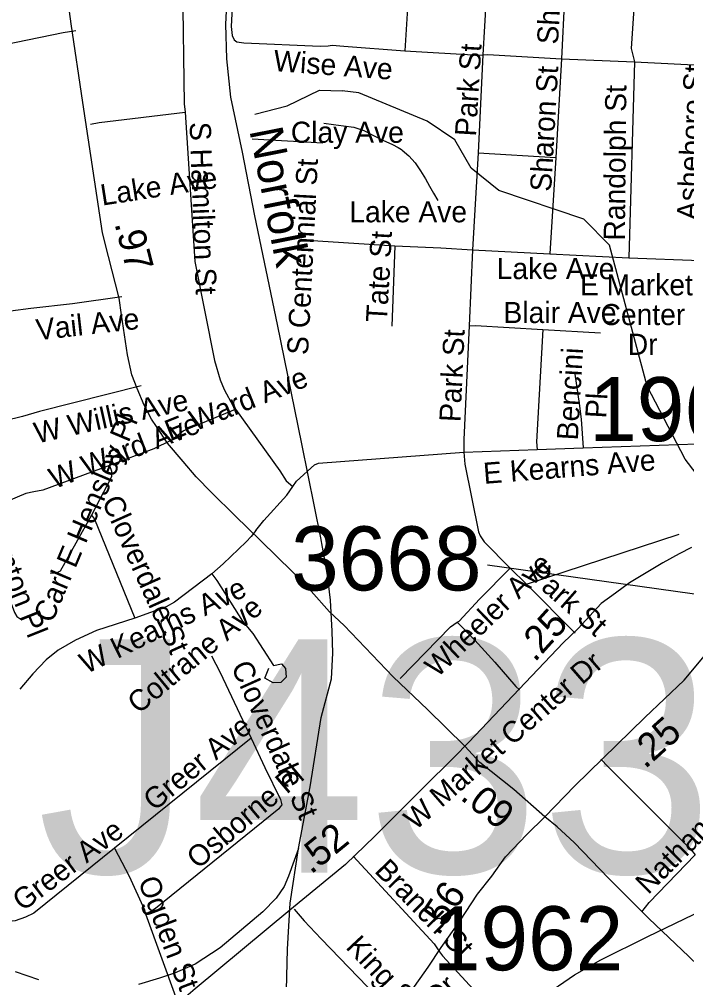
# Model space of a CAD drawing. Extents: x 1662474 to 1856135, y 779280 to 917889.
# Drawn here: x 1702628 to 1705631, y 797474 to 801794 of the extents above; entities that cross this region are included whole.
import ezdxf

# ---------------------------------------------------------------- set-up
doc = ezdxf.new("R2010")
doc.units = 0
for name, color, linetype in [('Cogo Default Point CELL', 7, 'Continuous'), ('Exist Hydrographic Misc Water Feature', 7, 'Continuous'), ('Exist Railroad Mainline', 7, 'Continuous'), ('Exist Railroad Mainline Label', 7, 'Continuous'), ('Exist Railroad Siding', 7, 'Continuous'), ('Exist Road Non-System Structure Non-Sys Other Number Label', 7, 'Continuous'), ('Exist Road Non-System Type 51', 7, 'Continuous'), ('Exist Road Non-System Type 51 Label', 7, 'Continuous'), ('Exist Road Primary US Mileage Hundredths English Label', 7, 'Continuous'), ('Exist Road Primary US UnDivided 4 Lane Attributed', 7, 'Continuous'), ('Exist Road Secondary Mileage Tenths English Label', 7, 'Continuous'), ('Exist Road Secondary Type 51 Attributed', 7, 'Continuous'), ('Exist Road Secondary Type 51 Label', 7, 'Continuous'), ('Exist Utilities Electrical Transmission Line', 7, 'Continuous'), ('Prop DGN Element Guardrail', 7, 'Continuous')]:
    doc.layers.add(name, color=color, linetype=linetype)

msp = doc.modelspace()

# ---------------------------------------------------------------- linework, layer by layer
at = {"layer": 'Cogo Default Point CELL'}
msp.add_line((1705743.6, 799197.4), (1704734.2, 799337.9), dxfattribs=at)
at = {"layer": 'Exist Hydrographic Misc Water Feature'}
for points in [[(1703687, 801367.3), (1703833.3, 801403.9), (1703978.1, 801474.6), (1704081, 801471.1)], [(1706601, 798213), (1706577, 798348), (1706572, 798673.1), (1706483, 799006.4), (1706318, 799183.7), (1706094, 799326.1), (1705772, 799621.6), (1705624, 799814.9), (1705452, 800143.4), (1705283, 800777), (1705167, 800894.3), (1704785, 801023.5), (1704661, 801124.5), (1704587, 801250.7), (1704463, 801335.3), (1704156, 801463), (1704081, 801471.1)]]:
    msp.add_lwpolyline(points, dxfattribs=at)
at = {"layer": 'Exist Railroad Mainline'}
for points in [[(1703884.2, 798063.9), (1703936.3, 798341.8), (1703986.3, 798653.6), (1704032.5, 798827.7), (1704039.1, 798943.5), (1704035.5, 799041.7), (1704028.2, 799181.7), (1704015.1, 799293.9), (1703984, 799461.9), (1703898.4, 799884.8), (1703789.5, 800421.4), (1703688.2, 800909.9), (1703631.6, 801196.6), (1703579.2, 801442.9), (1703562, 801614.9), (1703557, 801771.2), (1703568.1, 801976.8)], [(1703902.7, 796877.7), (1703877.1, 797023.6), (1703849.3, 797179.5), (1703827.9, 797366), (1703835.3, 797611.8), (1703846.1, 797818.5), (1703884.2, 798063.9)], [(1702716.6, 797473.2), (1702611, 797510)]]:
    msp.add_lwpolyline(points, dxfattribs=at)
at = {"layer": 'Exist Railroad Siding'}
msp.add_lwpolyline([(1703884.2, 798063.9), (1703838.4, 797940.6), (1703819.7, 797892.9), (1703783.3, 797840.6), (1703723, 797779.1), (1703532.1, 797618.1), (1703419.3, 797544.8), (1703326.5, 797504.4), (1703258.3, 797481), (1703164.9, 797453)], dxfattribs=at)
at = {"layer": 'Exist Road Non-System Type 51'}
for p, q in [((1704390.1, 802091), (1704363.1, 801651.9)), ((1704738.5, 802074.8), (1704713.8, 801633.8)), ((1705088.1, 802054.5), (1705066.9, 801616.2)), ((1704713.8, 801633.8), (1704692, 801193.4)), ((1705066.9, 801616.2), (1705041.4, 801171.4)), ((1705066.9, 801616.2), (1705395.9, 801601.8)), ((1705395.9, 801601.8), (1705370.1, 800720.9)), ((1705395.9, 801601.8), (1705723.2, 801585.8)), ((1703675.8, 801255.1), (1703993.4, 801237.2)), ((1704692, 801193.4), (1704667.4, 800756.4)), ((1704692, 801193.4), (1705041.4, 801171.4)), ((1705041.4, 801171.4), (1705014.9, 800739)), ((1703891.5, 800801.5), (1703970.5, 800796.5)), ((1703970.5, 800796.5), (1704316.9, 800773.9)), ((1704316.9, 800773.9), (1704303.4, 800412.9)), ((1704667.4, 800756.4), (1704651.4, 800415.4)), ((1704667.4, 800756.4), (1705014.9, 800739)), ((1705014.9, 800739), (1705370.1, 800720.9)), ((1705370.1, 800720.9), (1705692.8, 800708.1)), ((1704982.9, 800398.1), (1705241.9, 800383.2)), ((1705164.6, 799865.9), (1705677.9, 799884.2)), ((1704628, 799846.7), (1704957.9, 799858.5)), ((1704957.9, 799858.5), (1705164.6, 799865.9)), ((1704909.1, 799253.2), (1705596.1, 799478.2)), ((1704836.4, 799324.4), (1704909.1, 799253.2)), ((1704909.1, 799253.2), (1705128.5, 799032.8)), ((1703671.2, 798560.4), (1703056.1, 798065.1))]:
    msp.add_line(p, q, dxfattribs=at)
for points in [[(1703588.9, 802132.8), (1703594.9, 802113.6), (1703589.6, 801934.4), (1703580.8, 801761.4), (1703585.8, 801720.7), (1703594.4, 801700.7), (1703607, 801692.6), (1703638.5, 801687.6), (1703982.1, 801672.1), (1704016.9, 801674.4)], [(1705088.1, 802054.5), (1705357.9, 802037.4), (1705399.9, 802032.4), (1705403.9, 802025.1), (1705380.6, 801662.4), (1705395.9, 801601.8)], [(1703362.1, 801948.8), (1703370, 801413.9), (1703373.6, 801375.2)], [(1702882.9, 801741.4), (1702825.1, 801733.2), (1702401.2, 801645.9)], [(1704016.9, 801674.4), (1704035.9, 801676.4), (1704088.1, 801673.2), (1704363.1, 801651.9)], [(1704363.1, 801651.9), (1704695.9, 801631.9), (1704713.8, 801633.8)], [(1704713.8, 801633.8), (1704735.6, 801634.9), (1705066.9, 801616.2)], [(1702948.5, 801321.7), (1702987.6, 801328.9), (1703373.6, 801375.2)], [(1703373.6, 801375.2), (1703417.5, 800703.9), (1703506.8, 800259), (1703531.4, 800172.7), (1703549, 800128.9), (1703589.4, 800053.5), (1703600.9, 800039.6)], [(1703998.1, 801326.4), (1704042, 801319.8), (1704086.2, 801315), (1704133.4, 801308.7), (1704178.4, 801293), (1704221.1, 801271.4), (1704263.2, 801249.2), (1704306.4, 801230.4), (1704332.1, 801216.4)], [(1704332.1, 801216.4), (1704346.9, 801208.4), (1704350.9, 801205)], [(1704350.9, 801205), (1704381, 801180.1), (1704409.1, 801147.4), (1704433.6, 801112), (1704455.4, 801076.5), (1704473.8, 801042.7), (1704491.4, 801011.6), (1704510.9, 800978.4)], [(1704316.9, 800773.9), (1704524, 800765.9), (1704667.4, 800756.4)], [(1703089.1, 800545.6), (1702867.1, 800513.9), (1702679.4, 800493.4), (1702588.9, 800480.8)], [(1704651.4, 800415.4), (1704627.4, 799904.4), (1704628, 799846.7)], [(1704651.4, 800415.4), (1704681, 800416.8), (1704982.9, 800398.1)], [(1704982.9, 800398.1), (1704955.2, 799893.7), (1704957.9, 799858.5)], [(1705126.9, 800197.4), (1705146.4, 800065.6), (1705156, 799995.2), (1705164.6, 799865.9)], [(1703176, 800145.6), (1702718.2, 800029.6), (1702642.1, 800007.6)], [(1703310.1, 799898.7), (1703365.5, 799942.8), (1703600.9, 800039.6)], [(1703600.9, 800039.6), (1703800.1, 799762.9), (1703829.2, 799718.1), (1703858.4, 799692.9)], [(1702642.1, 800007.6), (1702188.4, 799895.8), (1702109.4, 799866.1)], [(1703310.1, 799898.7), (1703233.8, 799862.2), (1703033.8, 799786.4)], [(1703955.9, 799789.8), (1703974.4, 799796.9), (1704628, 799846.7)], [(1704628, 799846.7), (1704632.6, 799792.9), (1704693.9, 799488.9), (1704700.9, 799471.1), (1704719.4, 799444.1), (1704836.4, 799324.4)], [(1703033.8, 799786.4), (1702733.8, 799676.4), (1702693.1, 799667.9)], [(1703033.8, 799786.4), (1703043.2, 799760.6), (1703042.4, 799736.2), (1702953.1, 799564)], [(1703858.4, 799692.9), (1703874.6, 799717), (1703955.9, 799789.8)], [(1702693.1, 799667.9), (1702657.4, 799660.6), (1702439.6, 799569)], [(1703691.5, 799495), (1703728.2, 799539.6), (1703830.9, 799653.2), (1703858.4, 799692.9)], [(1702953.1, 799564), (1702811.8, 799310.8), (1702791.5, 799301.5), (1702767.4, 799303.1)], [(1702953.1, 799564), (1702965.8, 799545.6), (1703148.5, 799100.2)], [(1703691.5, 799495), (1703671.6, 799466.9), (1703649.2, 799444.1), (1703545.9, 799345.1), (1703494.1, 799299.4)], [(1704598.4, 799081.6), (1704606.1, 799086.1), (1704698.4, 799185.2), (1704836.4, 799324.4)], [(1703494.1, 799299.4), (1703326.6, 799172.2), (1703288.1, 799150.4), (1703148.5, 799100.2)], [(1703494.1, 799299.4), (1703517, 799269.8), (1703631.6, 799087.4), (1703678.6, 799030.7)], [(1702571.4, 799218.4), (1702606.8, 799125.2), (1702617.5, 799107.6), (1702635.6, 799095.2)], [(1703148.5, 799100.2), (1702975.8, 799045.1), (1702880.8, 799000.5), (1702803.6, 798956.9), (1702749, 798913.1), (1702689.4, 798849.9), (1702630.9, 798780.6)], [(1704342.1, 798828.9), (1704568.4, 799061.9), (1704598.4, 799081.6)], [(1704598.4, 799081.6), (1704677.4, 799000.8), (1704767.4, 798902.1), (1704861.9, 798793.2), (1704878.9, 798777.9)], [(1703678.6, 799030.7), (1703771.6, 798887.9), (1703807.2, 798895.5), (1703826.1, 798873.5), (1703829.2, 798835.4), (1703803.9, 798810.2), (1703769.8, 798808.9), (1703733.2, 798830.9), (1703750.6, 798875)], [(1703492, 798931.5), (1703532.1, 798855.4), (1703671.2, 798560.4)], [(1703671.2, 798560.4), (1703732.1, 798428.4), (1703803.1, 798284.8), (1703808.4, 798260.6), (1703802, 798252.2), (1703794.9, 798242.5), (1703240.1, 797795.2), (1703219.6, 797780.9), (1703196.2, 797770.1)], [(1705244.8, 798465.6), (1705276.8, 798431.2), (1705649.5, 798060.4), (1705668.4, 798036.2)], [(1703056.1, 798065.1), (1702692.9, 797774.2), (1702656.1, 797754.9), (1702609.1, 797739.1), (1702554.2, 797732.5), (1702488.4, 797735.2), (1702392.4, 797753.5), (1702207.5, 797796.9)], [(1703056.1, 798065.1), (1703121.9, 797939.6), (1703190.8, 797788.2), (1703196.2, 797770.1)], [(1704130.4, 798030.4), (1704494.9, 797635.2), (1704517.8, 797599.8)], [(1705428.5, 797779.8), (1705461.9, 797821), (1705668.4, 798036.2)], [(1703196.2, 797770.1), (1703336.6, 797382.4), (1703343.5, 797352.2)], [(1703865, 797792.1), (1703909.6, 797739.6), (1703985.8, 797658.8), (1704319.1, 797313.7)], [(1704517.8, 797599.8), (1704531.6, 797581.4), (1705036.1, 797034.7), (1705065.2, 796992.2)]]:
    msp.add_lwpolyline(points, dxfattribs=at)
at = {"layer": 'Exist Road Primary US UnDivided 4 Lane Attributed'}
for points in [[(1704023.2, 799128.4), (1703941.2, 799221.2), (1703856.4, 799308.1), (1703714.5, 799447.5), (1703598.9, 799560.4), (1703492.1, 799664.7), (1703424.4, 799736.3), (1703365.4, 799804.5), (1703294.9, 799886.7), (1703245, 799961.7), (1703223.1, 799995.8), (1703190.3, 800058), (1703159, 800133), (1703134, 800195.2), (1703115.3, 800284.6), (1703087.8, 800464.9), (1703077.2, 800538.6), (1703029.2, 800726), (1703002.2, 800833), (1702913.7, 801419.4), (1702861.3, 801773.7), (1702826.4, 802029.3)], [(1704632.2, 798523.9), (1704464.4, 798688.7), (1704309.9, 798836.5), (1704089.4, 799067.8), (1704023.2, 799128.4)], [(1704992, 798206.4), (1704852.5, 798329.2), (1704700.1, 798450.4), (1704632.2, 798523.9)], [(1706100.4, 797123), (1706060.3, 797167.7), (1706016.9, 797207.3), (1705814.5, 797411), (1705639.4, 797578.8), (1705459.4, 797750.1), (1705278.3, 797931.2), (1705123.4, 798090.8), (1705047.2, 798161.4), (1704992, 798206.4)]]:
    msp.add_lwpolyline(points, dxfattribs=at)
at = {"layer": 'Exist Road Secondary Type 51 Attributed'}
for points in [[(1705651.6, 799418.4), (1705596, 799389.2), (1705522.5, 799348.5), (1705441.1, 799300.1), (1705372.3, 799259.4), (1705309.8, 799212.5), (1705245.7, 799165.6), (1705142.4, 799054), (1705075, 798989.6), (1704876.7, 798780.5), (1704651, 798543.1), (1704632.2, 798523.9)], [(1704992, 798206.4), (1705126.4, 798345.7), (1705441.5, 798653.2), (1705618.2, 798821.2), (1705885.7, 799141.3)], [(1704632.2, 798523.9), (1704600.8, 798491.9), (1704427, 798319.9), (1704227, 798119.9), (1704096.2, 797991.9), (1703844.9, 797786.5), (1703419.5, 797432.7), (1703346.1, 797369.9), (1703192.9, 797237.2), (1702921.9, 796993.6), (1702843.5, 796926.3), (1702808, 796900.2), (1702682.8, 796827.3), (1702565.1, 796765.7)], [(1702565.1, 796765.7), (1702752.1, 796758), (1702933.3, 796784.2), (1703009.9, 796799.1), (1703051, 796810.3), (1703262.1, 796877.6), (1703570.3, 796974.7), (1703909.5, 797087.9), (1703975.8, 797113.6), (1704047.7, 797141.2), (1704165, 797202.1), (1704205.5, 797227.2), (1704271, 797279.1), (1704327.1, 797342.7), (1704388.1, 797418.2), (1704466.8, 797530), (1704526.2, 797619.2), (1704609.7, 797737.8), (1704689.6, 797858.6), (1704753.5, 797940.2), (1704815.7, 798027.2), (1704911.1, 798126.7), (1704992, 798206.4)]]:
    msp.add_lwpolyline(points, dxfattribs=at)
at = {"layer": 'Exist Utilities Electrical Transmission Line'}
msp.add_lwpolyline([(1704828.4, 797291.8), (1705125, 797495.5), (1705243.9, 797563.7), (1705455.5, 797668.7), (1705701.1, 797787.1)], dxfattribs=at)

# ---------------------------------------------------------------- texts
at = {"layer": 'Cogo Default Point CELL'}
for s, p in [('1961', (1705191.5, 799896.2)), ('3668', (1703850.9, 799225)), ('1962', (1704488.3, 797516.5))]:
    msp.add_text(s, height=288, dxfattribs=at).set_placement(p)
at = {"layer": 'Exist Railroad Mainline Label'}
msp.add_text('Norfolk', height=150, rotation=281.1679, dxfattribs=at).set_placement((1703662.5, 801294.1))
at = {"layer": 'Exist Road Non-System Structure Non-Sys Other Number Label'}
msp.add_text('J433', height=1049.86, dxfattribs=at).set_placement((1702707.6, 797955.3))
at = {"layer": 'Exist Road Non-System Type 51 Label'}
for s, rotation, p in [('Sharon St', 86.924, (1705051.5, 801678.6)), ('Park St', 86.5312, (1704682.3, 801264.7)), ('Wise Ave', 355.7612, (1703769.2, 801561.1)), ('Sharon St', 86.6897, (1705020.2, 801016.5)), ('Asheboro St', 87.2544, (1705680.2, 800888.2)), ('Randolph St', 89.4127, (1705352, 800797.9)), ('S Hamilton St', 272.0718, (1703394, 801330.3)), ('S Centennial St', 87.0908, (1703926.9, 800282.2)), ('Lake Ave', 8.8254, (1703001, 800955.2)), ('Tate St', 86.7974, (1704281.9, 800429.2)), ('Vail Ave', 6.452, (1702709, 800349.3)), ('Park St', 87.2937, (1704612.2, 799980.5)), ('Bencini ', 86.7579, (1705140.6, 799898.3)), ('E Ward Ave', 21.8129, (1703306.5, 799895)), ('W Willis Ave', 12.5694, (1702706.8, 799885)), ('   Pl', 86.7579, (1705262.4, 799891.4)), ('Carl E Hensley Pl', 67.0798, (1702775.6, 799073.4)), ('W Ward Ave', 21.2617, (1702785.3, 799679.8)), ('E Kearns Ave', 4.5557, (1704718.9, 799703.9)), ('Cloverdale St', 294.2153, (1702997.6, 799625.9)), ('Stanton Pl', 291.79, (1702452, 799548.9)), ('Wheeler Ave', 43.8933, (1704508.1, 798829.7)), ('Park St', 318.6842, (1704907.3, 799288.1)), ('W Kearns Ave', 26.0162, (1702929.2, 798847.8)), ('Coltrane Ave', 39.4887, (1703164.1, 798666.3)), ('Cloverdale St', 294.2153, (1703578.9, 798882.7)), ('Greer Ave', 39.6052, (1703235.5, 798229)), ('Nathan Hunt Dr', 45.0166, (1705457.3, 797853.4)), ('Osborne Pl', 40.2586, (1703431.9, 797968.3)), ('Greer Ave', 37.0416, (1702643.2, 797778.8)), ('Branch St', 314.4708, (1704222, 797960.2)), ('Ogden St', 290.888, (1703160.7, 797918.3)), ('King St', 313.1086, (1704092.6, 797618))]:
    msp.add_text(s, height=95, rotation=rotation, dxfattribs=at).set_placement(p)
for s, p in [('Clay Ave', (1703849.6, 801238)), ('Lake Ave', (1704112.6, 800880.4)), ('Lake Ave', (1704775.7, 800624.9)), ('Blair Ave', (1704806.3, 800427.3))]:
    msp.add_text(s, height=95, dxfattribs=at).set_placement(p)
at = {"layer": 'Exist Road Primary US Mileage Hundredths English Label'}
for s, rotation, p in [('.97', 284.3422, (1703055.7, 800875)), ('.09', 321.4841, (1704607.1, 798288.1))]:
    msp.add_text(s, height=125, rotation=rotation, dxfattribs=at).set_placement(p)
at = {"layer": 'Exist Road Secondary Mileage Tenths English Label'}
for s, rotation, p in [('.25', 47.9015, (1704947, 798898.9)), ('.25', 42.2839, (1705443, 798419.1)), ('.56', 56.4054, (1704513, 797667.8))]:
    msp.add_text(s, height=125, rotation=rotation, dxfattribs=at).set_placement(p)
at = {"layer": 'Exist Road Secondary Type 51 Label'}
for s, p in [('E Market', (1705150, 800551.8)), (' Center', (1705207.4, 800418.1)), (' Dr', (1705330.2, 800284.4))]:
    msp.add_text(s, height=95, dxfattribs=at).set_placement(p)
for s, rotation, p in [('W Market Center Dr', 41.1379, (1704409.8, 798142.9)), ('S College Dr', 44.0707, (1704088, 796934.9))]:
    msp.add_text(s, height=95, rotation=rotation, dxfattribs=at).set_placement(p)
at = {"layer": 'Prop DGN Element Guardrail'}
msp.add_text('.52', height=125, rotation=39.2778, dxfattribs=at).set_placement((1703940.4, 797945.2))

doc.saveas('drawing.dxf')
